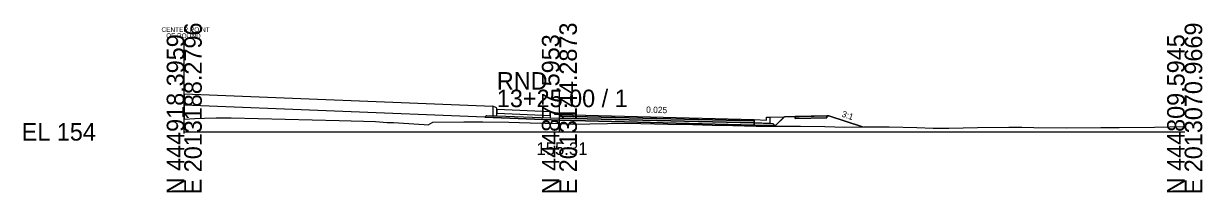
# Model space of a CAD drawing. Extents: x -26 to 163, y -10 to 7518.
# Drawn here: x -25.7 to 162.8, y 6490.3 to 6517.3 of the extents above; entities that cross this region are included whole.
import ezdxf

# ---------------------------------------------------------------- set-up
doc = ezdxf.new("R2010")
doc.units = 0
for name, color, linetype in [('Exist Cross Section Cell', 7, 'Continuous'), ('Exist XS Center Line Elevation Label', 7, 'Continuous'), ('Exist XS Ground Line', 7, 'Continuous'), ('Prop CMT Conc Surface', 7, 'Continuous'), ('Prop CMT Concrete Structures', 7, 'Continuous'), ('Prop CMT Pvmt Course 1', 7, 'Continuous'), ('Prop CMT Pvmt Course 1 CG', 7, 'Continuous'), ('Prop CMT Pvmt Course 2', 7, 'Continuous'), ('Prop CMT Pvmt Course 3', 7, 'Continuous'), ('Prop CMT Pvmt Surface', 7, 'Continuous'), ('Prop CMT Shear Line', 7, 'Continuous'), ('Prop CMT Shear Line Text', 7, 'Continuous'), ('Prop CMT Slope Grass', 7, 'Continuous'), ('Prop CMT Subgrade Earthwork', 7, 'Continuous'), ('Prop XS Earthwork Shape', 7, 'Continuous'), ('Prop XS SE Text', 7, 'Continuous'), ('Prop XS Side Slope Text', 7, 'Continuous')]:
    doc.layers.add(name, color=color, linetype=linetype)

msp = doc.modelspace()

# ---------------------------------------------------------------- linework, layer by layer
at = {"layer": 'Exist Cross Section Cell'}
for p, q in [((60, 6500), (60, 6506.75)), ((0, 6500), (60, 6500)), ((60, 6500), (160, 6500))]:
    msp.add_line(p, q, dxfattribs=at)
at = {"layer": 'Exist XS Ground Line'}
msp.add_lwpolyline([(0, 6502.05), (1.71, 6502.12), (3.24, 6502.18), (5.09, 6502.25), (6.32, 6502.24), (7.11, 6502.24), (7.53, 6502.24), (24.8, 6501.84), (30.57, 6501.66), (32.46, 6501.51), (33.17, 6501.47), (33.49, 6501.5), (37.54, 6501.25), (38.35, 6501.16), (39, 6501.1), (39.75, 6501.56), (44.71, 6501.58), (47.77, 6501.58), (51.93, 6501.55), (55.3, 6501.44), (60, 6501.31), (62.06, 6501.25), (67.69, 6501.35), (70.26, 6501.37), (73.03, 6501.34), (77.34, 6501.22), (81.34, 6501.19), (84.42, 6501.09), (87.74, 6501.04), (91.49, 6500.89), (94.98, 6500.91), (98.57, 6500.9), (102.44, 6500.83), (105.65, 6500.75), (108.62, 6500.78), (112.72, 6500.82), (117.15, 6500.68), (119.8, 6500.6), (122.26, 6500.61), (126.88, 6500.72), (131.86, 6500.73), (133.95, 6500.73), (135.9, 6500.7), (141.03, 6500.64), (146.57, 6500.67), (148.11, 6500.7), (149.54, 6500.69), (155.18, 6500.74), (160, 6500.85)], dxfattribs=at)
at = {"layer": 'Prop CMT Conc Surface'}
for points in [[(50, 6503.74), (49.96, 6503.85), (49.85, 6503.89), (49.34, 6504.08)], [(50, 6503.58), (50, 6503.74)], [(60, 6502.78), (59.25, 6502.8), (59.25, 6502.97), (58.5, 6503.22)], [(97.73, 6502.46), (102.73, 6502.56)], [(91.14, 6502), (93.14, 6501.87)], [(93.14, 6501.87), (93.14, 6502.37), (93.64, 6502.37)]]:
    msp.add_lwpolyline(points, dxfattribs=at)
at = {"layer": 'Prop CMT Concrete Structures'}
for points in [[(50, 6503.74), (49.96, 6503.85), (49.85, 6503.89), (49.34, 6504.08)], [(49.34, 6504.08), (49.34, 6502.58)], [(49.34, 6502.58), (50, 6502.58)], [(50, 6503.58), (50, 6503.74)], [(50, 6502.58), (50, 6503.58)], [(50, 6503.58), (50, 6502.99)], [(58.5, 6503.22), (50, 6503.56)], [(50, 6502.97), (58.5, 6502.63)], [(60, 6502.78), (59.25, 6502.8), (59.25, 6502.97), (58.5, 6503.22)], [(58.5, 6503.22), (58.5, 6502.24)], [(58.5, 6502.63), (58.5, 6503.22)], [(60, 6502.2), (60, 6502.78)], [(102.79, 6502.56), (97.73, 6502.46)], [(102.79, 6502.23), (102.79, 6502.56)], [(58.5, 6502.24), (60, 6502.2)], [(91.14, 6502), (93.14, 6501.87), (93.14, 6502.37), (93.64, 6502.37)], [(93.64, 6502.37), (93.64, 6501.35), (91.14, 6501.42)], [(91.14, 6501.42), (91.14, 6502)], [(97.73, 6502.46), (97.73, 6502.13)], [(97.73, 6502.13), (102.79, 6502.23)]]:
    msp.add_lwpolyline(points, dxfattribs=at)
at = {"layer": 'Prop CMT Pvmt Course 1'}
for points in [[(60, 6502.78), (91.14, 6502)], [(60, 6502.53), (60, 6502.78)], [(91.14, 6501.75), (60, 6502.53)], [(91.14, 6502), (91.14, 6501.75)]]:
    msp.add_lwpolyline(points, dxfattribs=at)
msp.add_lwpolyline([(60, 6502.53), (60, 6502.66), (60, 6502.66), (60, 6502.53)], close=True, dxfattribs=at)
at = {"layer": 'Prop CMT Pvmt Course 1 CG'}
for points in [[(60, 6501.86), (60, 6502.2)], [(91.14, 6501.42), (94.13, 6501.34), (94.47, 6501)], [(91.14, 6501.08), (91.14, 6501.42)], [(94.56, 6501), (91.14, 6501.08)]]:
    msp.add_lwpolyline(points, dxfattribs=at)
at = {"layer": 'Prop CMT Pvmt Course 2'}
for points in [[(60, 6502.2), (60, 6502.53)], [(60, 6502.53), (91.14, 6501.75)], [(91.14, 6501.42), (60, 6502.2)], [(91.14, 6501.75), (91.14, 6501.42)]]:
    msp.add_lwpolyline(points, dxfattribs=at)
at = {"layer": 'Prop CMT Pvmt Course 3'}
for points in [[(50, 6502.58), (58.5, 6502.24)], [(60, 6502.2), (91.14, 6501.42)], [(60, 6501.86), (60, 6502.2)], [(91.14, 6501.08), (60, 6501.86)], [(91.14, 6501.42), (91.14, 6501.08)]]:
    msp.add_lwpolyline(points, dxfattribs=at)
at = {"layer": 'Prop CMT Pvmt Surface'}
msp.add_lwpolyline([(60, 6502.78), (91.14, 6502)], dxfattribs=at)
at = {"layer": 'Prop CMT Shear Line'}
msp.add_line((0, 6499.72), (0, 6514.72), dxfattribs=at)
at = {"layer": 'Prop CMT Slope Grass'}
for p, q in [((49.34, 6504.06), (0, 6506.03)), ((48.06, 6502.34), (0, 6504.26))]:
    msp.add_line(p, q, dxfattribs=at)
msp.add_lwpolyline([(93.64, 6502.37), (103.1, 6502.56), (108.45, 6500.78)], dxfattribs=at)
at = {"layer": 'Prop CMT Subgrade Earthwork'}
for p, q in [((0, 6506.03), (0, 6502.05)), ((48.34, 6502.62), (48.06, 6502.34))]:
    msp.add_line(p, q, dxfattribs=at)
for points in [[(48.34, 6502.62), (49.34, 6502.58)], [(48.06, 6502.34), (60, 6501.86)], [(60, 6501.86), (91.14, 6501.08)], [(91.14, 6501.08), (94.56, 6501), (95.97, 6502.42)]]:
    msp.add_lwpolyline(points, dxfattribs=at)
at = {"layer": 'Prop XS Earthwork Shape'}
msp.add_lwpolyline([(70.26, 6501.37), (73.03, 6501.34), (77.34, 6501.22), (81.34, 6501.19), (84.42, 6501.09), (87.74, 6501.04), (91.49, 6500.89), (94.98, 6500.91), (98.57, 6500.9), (102.44, 6500.83), (105.65, 6500.75), (108.45, 6500.78), (103.1, 6502.56), (102.79, 6502.56), (102.79, 6502.23), (97.73, 6502.13), (97.73, 6502.46), (95.98, 6502.42), (94.56, 6501), (91.14, 6501.08), (60, 6501.86), (48.06, 6502.34), (0, 6504.26), (0, 6502.05), (1.71, 6502.12), (3.24, 6502.18), (5.09, 6502.25), (6.32, 6502.24), (7.11, 6502.24), (7.53, 6502.24), (24.8, 6501.84), (30.57, 6501.66), (32.46, 6501.51), (33.17, 6501.47), (33.49, 6501.5), (37.54, 6501.25), (38.35, 6501.16), (39, 6501.1), (39.75, 6501.56), (44.71, 6501.58), (47.77, 6501.58), (51.93, 6501.55), (55.3, 6501.44), (60, 6501.31), (62.06, 6501.25), (67.69, 6501.35)], close=True, dxfattribs=at)

# ---------------------------------------------------------------- texts
at = {"layer": 'Exist Cross Section Cell'}
for s, p in [('E 2013188.2796', (2.8, 6490)), ('E 2013144.2873', (62.8, 6490)), ('E 2013070.9669', (162.8, 6490)), ('N 444918.3959', (0, 6490)), ('N 444877.5953', (60, 6490)), ('N 444809.5945', (160, 6490))]:
    msp.add_text(s, height=2.8, rotation=90, dxfattribs=at).set_placement(p)
for s, p in [('RND', (50, 6506.75)), ('13+25.00 / 1', (50, 6503.95)), ('EL 154', (-26, 6498.6))]:
    msp.add_text(s, height=2.8, dxfattribs=at).set_placement(p)
at = {"layer": 'Exist XS Center Line Elevation Label'}
msp.add_text('155.31', height=2, dxfattribs=at).set_placement((56.32, 6496.31))
at = {"layer": 'Prop CMT Shear Line Text'}
for s, p in [('CENTER POINT', (-3.64, 6515.98)), ('OF ROUND', (-2.88, 6515))]:
    msp.add_text(s, height=0.75, dxfattribs=at).set_placement(p)
at = {"layer": 'Prop XS SE Text'}
msp.add_text('0.025', height=1, rotation=358.5613, dxfattribs=at).set_placement((73.87, 6503.06))
at = {"layer": 'Prop XS Side Slope Text'}
msp.add_text('3:1', height=1, rotation=341.5651, dxfattribs=at).set_placement((105.07, 6502.45))

doc.saveas('drawing.dxf')
